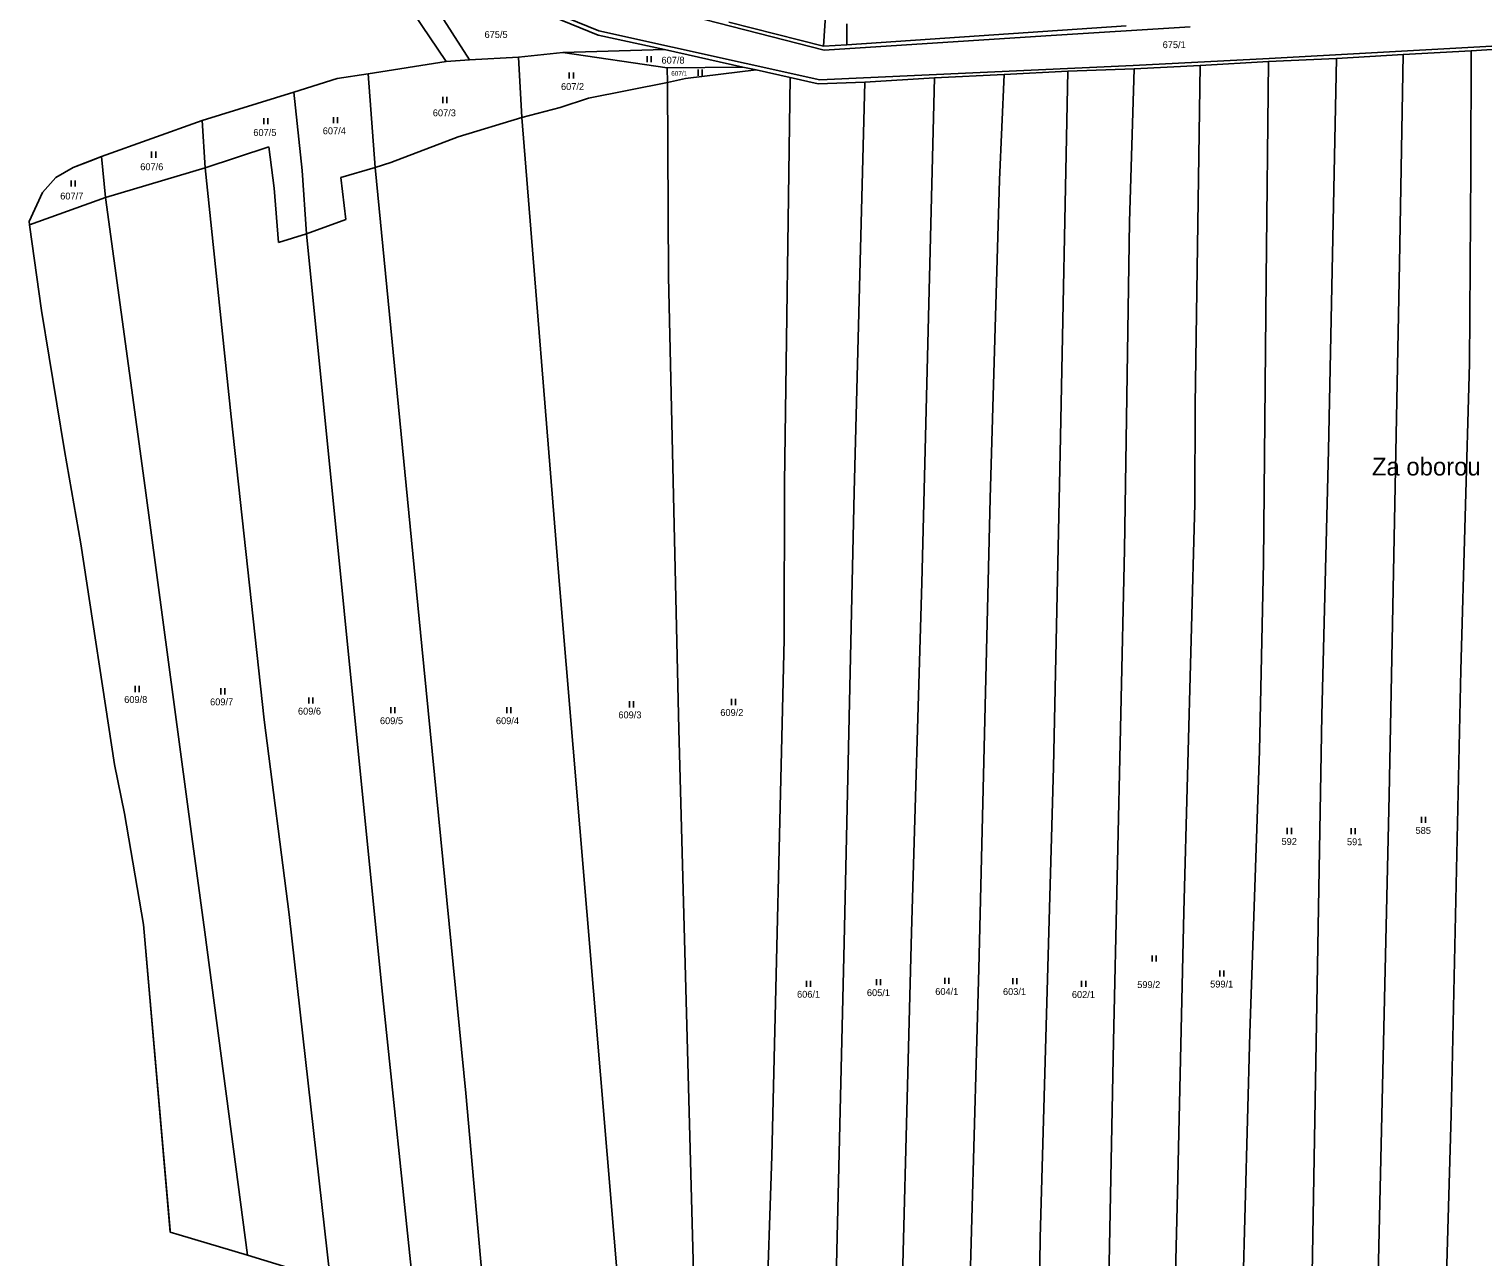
# Model space of a CAD drawing. Extents: x -747333 to -745433, y -1133152 to -1130600.
# Drawn here: x -747332.9 to -746974.4, y -1132588.2 to -1132285.5 of the extents above; entities that cross this region are included whole.
import ezdxf

# ---------------------------------------------------------------- set-up
doc = ezdxf.new("R2010")
doc.units = 0
for name, color, linetype in [('Vrstva 1', 7, 'Continuous'), ('Vrstva 13', 7, 'Continuous'), ('Vrstva 15', 7, 'Continuous'), ('Vrstva 18', 7, 'Continuous'), ('Vrstva 25', 7, 'Continuous'), ('Vrstva 4', 7, 'Continuous'), ('Vrstva 52', 7, 'Continuous'), ('Vrstva 6', 7, 'Continuous')]:
    doc.layers.add(name, color=color, linetype=linetype)

msp = doc.modelspace()

# ---------------------------------------------------------------- linework, layer by layer
at = {"layer": 'Vrstva 1'}
for points in [[(-747224.29, -1132293.07), (-747245.64, -1132259.69)], [(-747136.97, -1132289.67), (-747136.13, -1132275.75)], [(-747192.6, -1132286.93), (-747215.16, -1132277.65)], [(-747160.38, -1132283.74), (-747136.97, -1132289.67)], [(-747131.29, -1132284.16), (-747131.25, -1132289.37)], [(-747131.25, -1132289.37), (-747062.36, -1132284.69)], [(-747176.19, -1132290.5), (-747192.6, -1132286.93)], [(-747136.97, -1132289.67), (-747131.25, -1132289.37)], [(-746977.35, -1132290.83), (-746959.35, -1132289.69)], [(-747230, -1132293.43), (-747224.29, -1132293.07)], [(-747224.29, -1132293.07), (-747212.18, -1132292.42)], [(-747212.18, -1132292.42), (-747201.25, -1132291.26)], [(-747201.25, -1132291.26), (-747176.19, -1132290.5)], [(-747176.19, -1132290.5), (-747156.87, -1132294.81)], [(-747044.14, -1132294.41), (-747027.28, -1132293.41)], [(-747027.28, -1132293.41), (-747010.5, -1132292.69)], [(-747010.5, -1132292.69), (-746994.07, -1132291.76)], [(-746994.07, -1132291.76), (-746977.35, -1132290.83)], [(-747156.87, -1132294.81), (-747153.58, -1132295.54)], [(-747153.58, -1132295.54), (-747145.2, -1132297.4)], [(-747145.2, -1132297.4), (-747138.35, -1132298.93)], [(-747126.8, -1132298.51), (-747109.65, -1132297.48)], [(-747109.65, -1132297.48), (-747092.43, -1132296.62)], [(-747092.43, -1132296.62), (-747076.79, -1132295.83)], [(-747076.79, -1132295.83), (-747060.43, -1132295.27)], [(-747060.43, -1132295.27), (-747044.14, -1132294.41)], [(-747138.35, -1132298.93), (-747126.8, -1132298.51)]]:
    msp.add_lwpolyline(points, dxfattribs=at)
at = {"layer": 'Vrstva 13'}
for points in [[(-747230, -1132293.43), (-747248.16, -1132266.52)], [(-747249.27, -1132296.46), (-747230, -1132293.43)], [(-747256.92, -1132297.67), (-747249.27, -1132296.46)], [(-747290.17, -1132308.02), (-747267.6, -1132300.99)], [(-747267.6, -1132300.99), (-747256.92, -1132297.67)], [(-747315.01, -1132316.89), (-747290.17, -1132308.02)], [(-747322, -1132319.58), (-747315.01, -1132316.89)], [(-747329.55, -1132325.78), (-747326.26, -1132322.01)], [(-747326.26, -1132322.01), (-747322, -1132319.58)], [(-747332.87, -1132332.92), (-747329.55, -1132325.78)], [(-747332.76, -1132333.73), (-747332.87, -1132332.92)], [(-747329.82, -1132354.84), (-747332.76, -1132333.73)], [(-747324.1, -1132389.32), (-747329.82, -1132354.84)], [(-747320.12, -1132412.33), (-747324.1, -1132389.32)], [(-747311.81, -1132466.78), (-747320.12, -1132412.33)], [(-747309.37, -1132478.82), (-747311.81, -1132466.78)], [(-747304.7, -1132506.26), (-747309.37, -1132478.82)], [(-747298.07, -1132582.05), (-747304.7, -1132506.26)], [(-747295.89, -1132582.7), (-747298.07, -1132582.05)], [(-747279.04, -1132587.77), (-747295.89, -1132582.7)], [(-747267.98, -1132591.09), (-747279.04, -1132587.77)]]:
    msp.add_lwpolyline(points, dxfattribs=at)
at = {"layer": 'Vrstva 25'}
for p, q in [((-747180.48, -1132292.1), (-747180.48, -1132293.6)), ((-747179.48, -1132293.6), (-747179.48, -1132292.1)), ((-747199.68, -1132296.15), (-747199.68, -1132297.65)), ((-747198.68, -1132297.65), (-747198.68, -1132296.15)), ((-747167.92, -1132295.45), (-747167.92, -1132296.95)), ((-747166.92, -1132296.95), (-747166.92, -1132295.45)), ((-747230.89, -1132302.2), (-747230.89, -1132303.7)), ((-747229.89, -1132303.7), (-747229.89, -1132302.2)), ((-747274.99, -1132307.41), (-747274.99, -1132308.91)), ((-747273.99, -1132308.91), (-747273.99, -1132307.41)), ((-747257.84, -1132307.19), (-747257.84, -1132308.69)), ((-747256.84, -1132308.69), (-747256.84, -1132307.19)), ((-747302.65, -1132315.66), (-747302.65, -1132317.16)), ((-747301.65, -1132317.16), (-747301.65, -1132315.66)), ((-747322.49, -1132322.77), (-747322.49, -1132324.27)), ((-747321.49, -1132324.27), (-747321.49, -1132322.77)), ((-747306.74, -1132447.41), (-747306.74, -1132448.91)), ((-747305.74, -1132448.91), (-747305.74, -1132447.41)), ((-747285.62, -1132447.98), (-747285.62, -1132449.48)), ((-747284.62, -1132449.48), (-747284.62, -1132447.98)), ((-747263.93, -1132450.27), (-747263.93, -1132451.77)), ((-747262.93, -1132451.77), (-747262.93, -1132450.27)), ((-747184.85, -1132451.19), (-747184.85, -1132452.69)), ((-747183.85, -1132452.69), (-747183.85, -1132451.19)), ((-747159.73, -1132450.62), (-747159.73, -1132452.12)), ((-747158.73, -1132452.12), (-747158.73, -1132450.62)), ((-747243.66, -1132452.63), (-747243.66, -1132454.13)), ((-747242.66, -1132454.13), (-747242.66, -1132452.63)), ((-747215.12, -1132452.63), (-747215.12, -1132454.13)), ((-747214.12, -1132454.13), (-747214.12, -1132452.63)), ((-746989.61, -1132479.68), (-746989.61, -1132481.18)), ((-746988.61, -1132481.18), (-746988.61, -1132479.68)), ((-747022.65, -1132482.41), (-747022.65, -1132483.91)), ((-747021.65, -1132483.91), (-747021.65, -1132482.41)), ((-747006.89, -1132482.48), (-747006.89, -1132483.98)), ((-747005.89, -1132483.98), (-747005.89, -1132482.48)), ((-747056.01, -1132513.88), (-747056.01, -1132515.38)), ((-747055.01, -1132515.38), (-747055.01, -1132513.88)), ((-747123.92, -1132519.68), (-747123.92, -1132521.18)), ((-747122.92, -1132521.18), (-747122.92, -1132519.68)), ((-747107.11, -1132519.39), (-747107.11, -1132520.89)), ((-747106.11, -1132520.89), (-747106.11, -1132519.39)), ((-747090.34, -1132519.42), (-747090.34, -1132520.92)), ((-747089.34, -1132520.92), (-747089.34, -1132519.42)), ((-747039.31, -1132517.56), (-747039.31, -1132519.06)), ((-747038.31, -1132519.06), (-747038.31, -1132517.56)), ((-747141.18, -1132520.08), (-747141.18, -1132521.58)), ((-747140.18, -1132521.58), (-747140.18, -1132520.08)), ((-747073.36, -1132520.13), (-747073.36, -1132521.63)), ((-747072.36, -1132521.63), (-747072.36, -1132520.13))]:
    msp.add_line(p, q, dxfattribs=at)
at = {"layer": 'Vrstva 4'}
for points in [[(-747192.4, -1132285.87), (-747215.24, -1132276.52)], [(-747175.98, -1132280.66), (-747136.87, -1132290.65)], [(-747137.94, -1132298.01), (-747192.4, -1132285.87)], [(-747082.22, -1132287.12), (-747046.57, -1132284.9)], [(-747136.87, -1132290.65), (-747082.22, -1132287.12)], [(-746927.68, -1132287.24), (-747027.14, -1132292.69)], [(-747027.14, -1132292.69), (-747060.64, -1132294.41)], [(-747060.64, -1132294.41), (-747137.94, -1132298.01)]]:
    msp.add_lwpolyline(points, dxfattribs=at)
at = {"layer": 'Vrstva 52'}
msp.add_lwpolyline([(-747267.98, -1132591.09), (-747279.04, -1132587.77), (-747295.89, -1132582.7), (-747298.07, -1132582.05), (-747298.11, -1132581.57), (-747304.7, -1132506.26), (-747309.37, -1132478.82), (-747311.81, -1132466.78), (-747320.12, -1132412.33), (-747324.1, -1132389.32), (-747329.82, -1132354.84), (-747332.76, -1132333.73), (-747332.78, -1132333.6), (-747332.87, -1132332.92), (-747329.55, -1132325.78), (-747326.26, -1132322.01), (-747322, -1132319.58), (-747317.22, -1132317.74), (-747315.01, -1132316.89), (-747290.17, -1132308.02), (-747267.6, -1132300.99), (-747256.92, -1132297.67), (-747249.27, -1132296.46), (-747230, -1132293.43), (-747248.16, -1132266.52)], dxfattribs=at)
at = {"layer": 'Vrstva 6'}
for points in [[(-747211.41, -1132307.23), (-747212.18, -1132292.42)], [(-747175.58, -1132295.03), (-747201.25, -1132291.26)], [(-747027.28, -1132293.41), (-747027.87, -1132347.05)], [(-747012.54, -1132389.31), (-747010.5, -1132292.69)], [(-746995.01, -1132343.27), (-746994.07, -1132291.76)], [(-746977.44, -1132319.92), (-746977.35, -1132290.83)], [(-747247.52, -1132319.59), (-747249.27, -1132296.46)], [(-747175.58, -1132295.03), (-747156.87, -1132294.81)], [(-747175.58, -1132295.03), (-747175.44, -1132298.6)], [(-747171.01, -1132297.6), (-747153.58, -1132295.54)], [(-747145.2, -1132297.4), (-747146.59, -1132397.3)], [(-747112.78, -1132422), (-747109.65, -1132297.48)], [(-747092.43, -1132296.62), (-747093.64, -1132322.66)], [(-747076.79, -1132295.83), (-747078.66, -1132390.05)], [(-747060.43, -1132295.27), (-747061.53, -1132332.94)], [(-747045.39, -1132378.05), (-747044.14, -1132294.41)], [(-747265.5, -1132320.3), (-747267.6, -1132300.99)], [(-747175.44, -1132298.6), (-747194.92, -1132302.52)], [(-747175.44, -1132298.6), (-747171.01, -1132297.6)], [(-747175.25, -1132346.52), (-747175.44, -1132298.6)], [(-747126.8, -1132298.51), (-747129.46, -1132399.59)], [(-747194.92, -1132302.52), (-747201.92, -1132304.81)], [(-747289.48, -1132319.66), (-747290.17, -1132308.02)], [(-747211.41, -1132307.23), (-747227.11, -1132312.02)], [(-747201.92, -1132304.81), (-747211.41, -1132307.23)], [(-747211.41, -1132307.23), (-747202.09, -1132422.47)], [(-747273.78, -1132314.52), (-747289.48, -1132319.66)], [(-747272.43, -1132324.65), (-747273.78, -1132314.52)], [(-747227.11, -1132312.02), (-747243.67, -1132318.37)], [(-747314.03, -1132326.94), (-747315.01, -1132316.89)], [(-747243.67, -1132318.37), (-747247.52, -1132319.59)], [(-747289.48, -1132319.66), (-747314.03, -1132326.94)], [(-747289.48, -1132319.66), (-747283.02, -1132381.07)], [(-747264.5, -1132335.93), (-747265.5, -1132320.3)], [(-747247.52, -1132319.59), (-747256.01, -1132322.08)], [(-747256.01, -1132322.08), (-747254.8, -1132332.44)], [(-747247.52, -1132319.59), (-747236.05, -1132437.6)], [(-746977.72, -1132367.88), (-746977.44, -1132319.92)], [(-747271.36, -1132338.08), (-747272.43, -1132324.65)], [(-747093.64, -1132322.66), (-747095.93, -1132401.18)], [(-747314.03, -1132326.94), (-747332.76, -1132333.73)], [(-747304.27, -1132398.56), (-747314.03, -1132326.94)], [(-747254.8, -1132332.44), (-747264.5, -1132335.93)], [(-747061.53, -1132332.94), (-747062.8, -1132413.73)], [(-747264.5, -1132335.93), (-747271.36, -1132338.08)], [(-747245.9, -1132521.85), (-747264.5, -1132335.93)], [(-746997.51, -1132474.32), (-746995.01, -1132343.27)], [(-747172.69, -1132458.03), (-747175.25, -1132346.52)], [(-747027.87, -1132347.05), (-747028.52, -1132416.99)], [(-746979.85, -1132443.55), (-746977.72, -1132367.88)], [(-747045.42, -1132402.53), (-747045.39, -1132378.05)], [(-747283.02, -1132381.07), (-747274.87, -1132455.74)], [(-747078.66, -1132390.05), (-747080.33, -1132467.43)], [(-747014.17, -1132454.62), (-747012.54, -1132389.31)], [(-747146.59, -1132397.3), (-747146.72, -1132435.98)], [(-747292.71, -1132484.51), (-747304.27, -1132398.56)], [(-747129.46, -1132399.59), (-747131.89, -1132510.66)], [(-747095.93, -1132401.18), (-747098.72, -1132517.12)], [(-747048.2, -1132503.11), (-747045.42, -1132402.53)], [(-747062.8, -1132413.73), (-747065.53, -1132535.08)], [(-747028.52, -1132416.99), (-747029.51, -1132463.38)], [(-747202.09, -1132422.47), (-747186.96, -1132603.22)], [(-747115.35, -1132508.1), (-747112.78, -1132422)], [(-747146.72, -1132435.98), (-747149.71, -1132563.34)], [(-747236.05, -1132437.6), (-747225.2, -1132547.83)], [(-746982.29, -1132553.18), (-746979.85, -1132443.55)], [(-747017.56, -1132654.05), (-747014.17, -1132454.62)], [(-747274.87, -1132455.74), (-747268.74, -1132503.72)], [(-747168.69, -1132604.22), (-747172.69, -1132458.03)], [(-747029.51, -1132463.38), (-747031.93, -1132533.05)], [(-747080.33, -1132467.43), (-747083.61, -1132583.5)], [(-747001.71, -1132657.34), (-746997.51, -1132474.32)], [(-747289.57, -1132508.15), (-747292.71, -1132484.51)], [(-747268.74, -1132503.72), (-747258.75, -1132592.75)], [(-747049.83, -1132575.85), (-747048.2, -1132503.11)], [(-747279.04, -1132587.77), (-747289.57, -1132508.15)], [(-747118.49, -1132631.03), (-747115.35, -1132508.1)], [(-747131.89, -1132510.66), (-747134.02, -1132600.6)], [(-747098.72, -1132517.12), (-747102.15, -1132640.46)], [(-747238.06, -1132596.46), (-747245.9, -1132521.85)], [(-747031.93, -1132533.05), (-747033.64, -1132597.08)], [(-747065.53, -1132535.08), (-747067.23, -1132623.45)], [(-747225.2, -1132547.83), (-747220.55, -1132599.6)], [(-746985.61, -1132669.47), (-746982.29, -1132553.18)], [(-747149.71, -1132563.34), (-747151.14, -1132604.73)], [(-747052.26, -1132674.28), (-747049.83, -1132575.85)], [(-747083.61, -1132583.5), (-747084.89, -1132682.58)]]:
    msp.add_lwpolyline(points, dxfattribs=at)

# ---------------------------------------------------------------- texts
at = {"layer": 'Vrstva 15'}
msp.add_text('Za oborou', height=4.4, dxfattribs=at).set_placement((-747001.797797, -1132395.52))
at = {"layer": 'Vrstva 18'}
for s, height, p in [('675/5', 1.7, (-747220.58, -1132287.65)), ('675/1', 1.7, (-747053.39, -1132290.15)), ('607/8', 1.7, (-747176.95, -1132293.98)), ('607/1', 1.14, (-747174.55, -1132296.95)), ('607/2', 1.7, (-747201.73, -1132300.48)), ('607/3', 1.7, (-747233.33, -1132306.96)), ('607/5', 1.7, (-747277.58, -1132311.8)), ('607/4', 1.7, (-747260.46, -1132311.39)), ('607/6', 1.7, (-747305.46, -1132320.25)), ('607/7', 1.7, (-747325.19, -1132327.47)), ('609/8', 1.7, (-747309.42, -1132451.61)), ('609/7', 1.7, (-747288.24, -1132452.18)), ('609/6', 1.7, (-747266.58, -1132454.47)), ('609/5', 1.7, (-747246.36, -1132456.83)), ('609/4', 1.7, (-747217.77, -1132456.83)), ('609/3', 1.7, (-747187.58, -1132455.39)), ('609/2', 1.7, (-747162.45, -1132454.82)), ('585', 1.7, (-746991.04, -1132483.88)), ('592', 1.7, (-747024.08, -1132486.61)), ('591', 1.7, (-747007.95, -1132486.68)), ('606/1', 1.7, (-747143.53, -1132524.28)), ('605/1', 1.7, (-747126.31, -1132523.88)), ('604/1', 1.7, (-747109.46, -1132523.59)), ('603/1', 1.7, (-747092.76, -1132523.62)), ('602/1', 1.7, (-747075.77, -1132524.33)), ('599/2', 1.7, (-747059.66, -1132521.9)), ('599/1', 1.7, (-747041.68, -1132521.76))]:
    msp.add_text(s, height=height, dxfattribs=at).set_placement(p)

doc.saveas('drawing.dxf')
